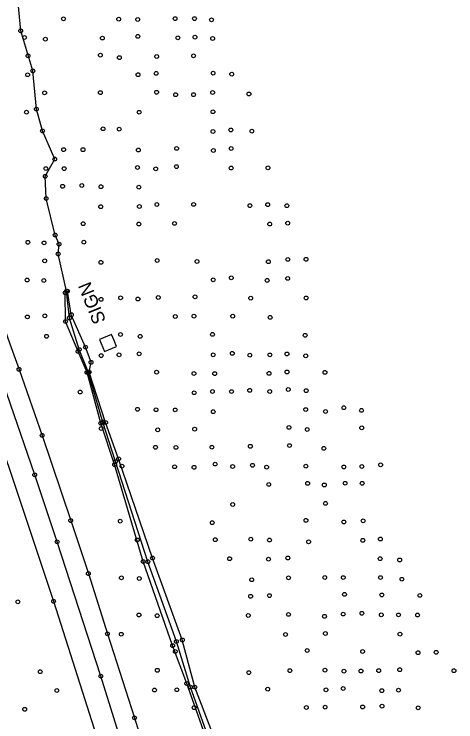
# Model space of a CAD drawing. Extents: x 20503438 to 20508873, y 7964251 to 7984667.
# Drawn here: x 20506445 to 20506678.1, y 7975096.9 to 7975470.8 of the extents above; entities that cross this region are included whole.
import ezdxf

# ---------------------------------------------------------------- set-up
doc = ezdxf.new("R2010")
doc.units = 0
for name, color, linetype in [('SurBreakLine', 7, 'Continuous'), ('SurDrainageArrowDown', 7, 'Continuous'), ('SurEdgeRoadPaved', 7, 'Continuous'), ('SurRoadPoints', 7, 'Continuous'), ('SurSurveyPoints', 7, 'Continuous')]:
    doc.layers.add(name, color=color, linetype=linetype)

msp = doc.modelspace()

# ---------------------------------------------------------------- linework, layer by layer
at = {"layer": 'SurBreakLine'}
for points in [[(20506349.14, 7975482.98), (20506362.94, 7975447.73), (20506373.06, 7975421.29), (20506389.9, 7975376.81), (20506416.68, 7975304.59), (20506442.42, 7975230.98), (20506465.81, 7975160.63), (20506487.25, 7975093.26), (20506498.75, 7975056.68), (20506509.78, 7975020.48), (20506520.41, 7974984.15), (20506530.78, 7974947.69), (20506540.38, 7974913.1), (20506559, 7974844.57), (20506576.27, 7974776.6), (20506593.8, 7974705.89)], [(20506563.33, 7975032.31), (20506557.73, 7975045.49), (20506545.09, 7975091.83), (20506536.07, 7975117.23), (20506528.64, 7975137.21), (20506513.06, 7975181.68), (20506498.04, 7975232.83), (20506490.75, 7975254.66), (20506483.47, 7975281.58), (20506478.73, 7975292.65), (20506472.08, 7975308.47), (20506471.96, 7975323.59)], [(20506564.68, 7975032.65), (20506560.23, 7975047), (20506548.72, 7975093.3), (20506540.37, 7975115.26), (20506533.76, 7975140.2), (20506518.04, 7975183.5), (20506500.13, 7975235.89), (20506493.28, 7975255.12), (20506484.64, 7975281.71), (20506485.6, 7975286.88), (20506482.64, 7975294.9), (20506475.18, 7975312.04), (20506473.09, 7975324.52)]]:
    msp.add_lwpolyline(points, dxfattribs=at)
at = {"layer": 'SurDrainageArrowDown'}
msp.add_lwpolyline([(20506546.26, 7975092.07), (20506538.01, 7975115.31), (20506530.61, 7975139.43), (20506515.56, 7975181.56), (20506498.53, 7975234.48), (20506491.82, 7975255.33), (20506484.04, 7975281.9), (20506479.4, 7975293.63), (20506474.15, 7975310.3), (20506472.62, 7975324.49), (20506468.26, 7975344.14), (20506468.69, 7975349.33), (20506466.66, 7975354.12), (20506461.94, 7975373.46), (20506461.41, 7975385.16), (20506466.43, 7975394.26), (20506459.99, 7975409.1), (20506456.74, 7975420.67), (20506454.88, 7975440.82), (20506448.47, 7975462.02), (20506446.23, 7975486.24)], dxfattribs=at)
at = {"layer": 'SurEdgeRoadPaved'}
for points in [[(20506367.4, 7975497.02), (20506382.84, 7975458.29), (20506396.34, 7975422.39), (20506402.33, 7975406.46), (20506419.54, 7975360.34), (20506427.81, 7975337.94), (20506435.05, 7975318.28), (20506442.77, 7975296.67), (20506447.6, 7975283.16), (20506459.75, 7975248.31), (20506474.87, 7975203.27), (20506484.19, 7975175.26), (20506494.28, 7975143.45), (20506508.53, 7975099.05), (20506530.67, 7975027.95), (20506542.03, 7974988.95), (20506557.31, 7974934.61), (20506564.1, 7974910.06), (20506570.08, 7974888.15), (20506579.93, 7974851.7), (20506590.35, 7974810.45), (20506601.11, 7974767.59), (20506615.26, 7974710.46)], [(20506618.24, 7974651.55), (20506601.4, 7974722.56), (20506592.63, 7974758.41), (20506583.52, 7974795.39), (20506564.42, 7974869.18), (20506554.39, 7974905.89), (20506543.98, 7974943.66), (20506534.13, 7974978.72), (20506523.8, 7975014.27), (20506515.58, 7975041.4), (20506512.29, 7975052.25), (20506490.77, 7975121.09), (20506467.72, 7975192.09), (20506455.87, 7975227.47), (20506443.11, 7975264.71), (20506430.35, 7975301.25), (20506417.72, 7975336.15), (20506403.48, 7975374.04), (20506389.38, 7975412.58), (20506375.71, 7975448.39), (20506362.64, 7975481.5)]]:
    msp.add_lwpolyline(points, dxfattribs=at)
at = {"layer": 'SurRoadPoints'}
msp.add_lwpolyline([(20506497.74, 7975298.42), (20506497.74, 7975298.42), (20506496.45, 7975301.59), (20506490.1, 7975299.02), (20506492.67, 7975292.67), (20506499.02, 7975295.24), (20506497.74, 7975298.41)], dxfattribs=at)
at = {"layer": 'SurSurveyPoints'}
for centre in [(20506471.07, 7975468.33), (20506500.17, 7975468.16), (20506510.21, 7975467.98), (20506529.94, 7975468.46), (20506540.21, 7975468.47), (20506549.17, 7975467.83), (20506448.47, 7975462.02), (20506450.5, 7975458.5), (20506461.48, 7975457.62), (20506491.56, 7975458.18), (20506510.25, 7975459.07), (20506531.36, 7975458.34), (20506540.42, 7975458.65), (20506549.77, 7975457.97), (20506452.35, 7975448.83), (20506490.51, 7975449.18), (20506500.52, 7975447.84), (20506520.24, 7975448.42), (20506539.69, 7975448.83), (20506452.1, 7975438.8), (20506454.88, 7975440.82), (20506510.4, 7975438.85), (20506519.98, 7975439.52), (20506550, 7975439.66), (20506559.81, 7975439.09), (20506461.07, 7975429.24), (20506490.51, 7975429.36), (20506520.2, 7975429.56), (20506530.24, 7975428.27), (20506539.69, 7975428.29), (20506549.75, 7975429.45), (20506568.93, 7975428.66), (20506456.74, 7975420.67), (20506451.54, 7975419.04), (20506510.99, 7975419), (20506549.92, 7975419.25), (20506459.99, 7975409.1), (20506491.91, 7975410.28), (20506500.47, 7975410.05), (20506549.94, 7975408.84), (20506559.37, 7975409.65), (20506570.44, 7975409), (20506471.11, 7975399.25), (20506481.34, 7975399.23), (20506510.56, 7975399.02), (20506530.74, 7975399.89), (20506550.16, 7975398.82), (20506559.51, 7975399.86), (20506466.43, 7975394.26), (20506510.1, 7975389.81), (20506530.64, 7975390.27), (20506559.54, 7975389.51), (20506578.95, 7975389.63), (20506461.73, 7975389.24), (20506471.42, 7975389.23), (20506519.73, 7975389.08), (20506461.41, 7975385.16), (20506470.6, 7975379.88), (20506480.69, 7975380.28), (20506490.82, 7975379.65), (20506510.83, 7975379.45), (20506461.94, 7975373.46), (20506490.69, 7975369.11), (20506511.09, 7975369.23), (20506520.34, 7975370.24), (20506539.74, 7975370.3), (20506569.42, 7975369.68), (20506578.82, 7975370.21), (20506588.93, 7975369.63), (20506481.4, 7975360.13), (20506510.79, 7975359.94), (20506529.61, 7975360.27), (20506579.89, 7975359.92), (20506589.36, 7975360.37), (20506466.66, 7975354.12), (20506452.27, 7975350.29), (20506460.8, 7975349.97), (20506468.69, 7975349.33), (20506481.8, 7975350.39), (20506468.26, 7975344.14), (20506589.46, 7975341.24), (20506599.05, 7975341.33), (20506461.14, 7975340.51), (20506490.83, 7975339.69), (20506520.46, 7975340.69), (20506541.52, 7975340.12), (20506579.16, 7975340.03), (20506451.86, 7975330.37), (20506460.64, 7975330.1), (20506550.06, 7975330.48), (20506559.61, 7975331.5), (20506578.51, 7975330.17), (20506589.36, 7975331.21), (20506471.96, 7975323.59), (20506472.62, 7975324.49), (20506473.09, 7975324.52), (20506490.87, 7975320.15), (20506501.18, 7975320.94), (20506510.36, 7975320.33), (20506521.06, 7975321.14), (20506540.47, 7975321.51), (20506569.83, 7975320.79), (20506599.11, 7975320.88), (20506461.18, 7975311.44), (20506475.18, 7975312.04), (20506530.04, 7975311.09), (20506539.91, 7975311.24), (20506560.35, 7975311.24), (20506451.98, 7975310.88), (20506472.08, 7975308.47), (20506474.15, 7975310.3), (20506580.11, 7975310.65), (20506462.12, 7975300.63), (20506501.11, 7975301.56), (20506511.52, 7975300.61), (20506549.71, 7975301.64), (20506598.59, 7975301.16), (20506478.73, 7975292.65), (20506479.4, 7975293.63), (20506482.64, 7975294.9), (20506490.92, 7975290.42), (20506500.37, 7975290.86), (20506511, 7975291.4), (20506550.07, 7975290.82), (20506560.12, 7975291.61), (20506569.34, 7975290.68), (20506579.97, 7975290.8), (20506588.98, 7975291.3), (20506598.88, 7975290.34), (20506485.6, 7975286.88), (20506447.6, 7975283.16), (20506483.47, 7975281.58), (20506484.04, 7975281.9), (20506484.64, 7975281.71), (20506520.18, 7975281.68), (20506579.53, 7975281.06), (20506589, 7975281.8), (20506609.05, 7975281.56), (20506539.88, 7975281.01), (20506550.84, 7975280.92), (20506479.84, 7975271.2), (20506539.99, 7975270.81), (20506549.65, 7975271.49), (20506559.7, 7975271.43), (20506569.31, 7975272.08), (20506579.89, 7975271.45), (20506589.68, 7975272.51), (20506599.13, 7975271.91), (20506619.03, 7975262.89), (20506510.11, 7975262.07), (20506519.9, 7975261.82), (20506530.02, 7975261.75), (20506550.07, 7975260.78), (20506598.87, 7975261.92), (20506609.3, 7975260.91), (20506628.3, 7975261.48), (20506491.82, 7975255.33), (20506493.28, 7975255.12), (20506490.75, 7975254.66), (20506490.89, 7975251.94), (20506520.78, 7975251.21), (20506540.27, 7975251.57), (20506590.05, 7975252.49), (20506599.68, 7975251.4), (20506628.44, 7975252.26), (20506459.75, 7975248.31), (20506519.62, 7975242), (20506530.41, 7975241.93), (20506549.37, 7975242.02), (20506569.65, 7975242.52), (20506590.3, 7975242.9), (20506608.48, 7975241.42), (20506498.04, 7975232.83), (20506498.53, 7975234.48), (20506500.13, 7975235.89), (20506551.11, 7975233.12), (20506570.81, 7975232.5), (20506638.42, 7975232.75), (20506501.9, 7975232.01), (20506529.7, 7975231.71), (20506539.96, 7975231.42), (20506560.32, 7975231.86), (20506578.24, 7975231.51), (20506598.94, 7975232.03), (20506618.96, 7975231.61), (20506628.49, 7975231.85), (20506455.87, 7975227.47), (20506579.38, 7975222.38), (20506599.87, 7975222.92), (20506608.7, 7975222.11), (20506619.7, 7975223), (20506628.64, 7975222.98), (20506560.33, 7975211.75), (20506609.31, 7975212.35), (20506474.87, 7975203.27), (20506501, 7975202.97), (20506599, 7975203.39), (20506619.02, 7975202.55), (20506629.2, 7975203.12), (20506549.55, 7975202.16), (20506467.72, 7975192.09), (20506509.98, 7975193.03), (20506551.16, 7975193.19), (20506569.87, 7975193.47), (20506579.77, 7975192.99), (20506600.4, 7975192.08), (20506629.01, 7975192.84), (20506638.28, 7975193.54), (20506513.06, 7975181.68), (20506515.56, 7975181.56), (20506518.04, 7975183.5), (20506558.72, 7975183.14), (20506579.21, 7975182.9), (20506589.42, 7975183.51), (20506638.2, 7975183.14), (20506648.46, 7975182.47), (20506484.19, 7975175.26), (20506501.61, 7975173.06), (20506511.06, 7975172.7), (20506589.76, 7975173.06), (20506608.93, 7975173.23), (20506618.69, 7975173.17), (20506638.32, 7975173.17), (20506570.38, 7975172.02), (20506649.64, 7975172.28), (20506569.8, 7975163.28), (20506579.72, 7975163.65), (20506619.33, 7975164.31), (20506639.02, 7975164), (20506659.13, 7975163.74), (20506446.92, 7975160.35), (20506465.81, 7975160.63), (20506628.53, 7975154.3), (20506510.88, 7975153.4), (20506520.47, 7975153.02), (20506568.56, 7975153.13), (20506589.82, 7975153.7), (20506608.78, 7975152.69), (20506618.66, 7975153.88), (20506638.77, 7975153.47), (20506647.86, 7975153.45), (20506657.91, 7975153.36), (20506494.28, 7975143.45), (20506501.55, 7975143.23), (20506588.19, 7975143.07), (20506609.26, 7975143.62), (20506648.6, 7975143.28), (20506530.61, 7975139.43), (20506533.76, 7975140.2), (20506528.64, 7975137.21), (20506530.03, 7975134.15), (20506599.63, 7975134.63), (20506628.91, 7975134.1), (20506658.17, 7975133.47), (20506667.7, 7975133.7), (20506520.57, 7975124.18), (20506590.54, 7975124.02), (20506609.03, 7975124.27), (20506637.38, 7975123.99), (20506648.48, 7975124.48), (20506458.77, 7975123.45), (20506490.77, 7975121.09), (20506568.83, 7975122.97), (20506619.07, 7975123.72), (20506628.02, 7975123.78), (20506677.1, 7975123.95), (20506536.07, 7975117.23), (20506467.55, 7975113.53), (20506519.08, 7975113.77), (20506530.88, 7975113.9), (20506538.01, 7975115.31), (20506540.37, 7975115.26), (20506578.82, 7975114.2), (20506609.56, 7975113.87), (20506618.67, 7975114.58), (20506639.02, 7975113.42), (20506647.83, 7975113.67), (20506450.59, 7975103.57), (20506540.03, 7975104.44), (20506599.22, 7975104.5), (20506609.1, 7975104.69), (20506628.91, 7975104.82), (20506639.15, 7975105.25), (20506658.21, 7975104.38), (20506508.53, 7975099.05)]:
    msp.add_circle(centre, 1, dxfattribs=at)

# ---------------------------------------------------------------- texts
at = {"layer": 'SurRoadPoints'}
msp.add_text('SIGN', height=6.995, rotation=112.0182, dxfattribs=at).set_placement((20506493.6, 7975308.83))

doc.saveas('drawing.dxf')
